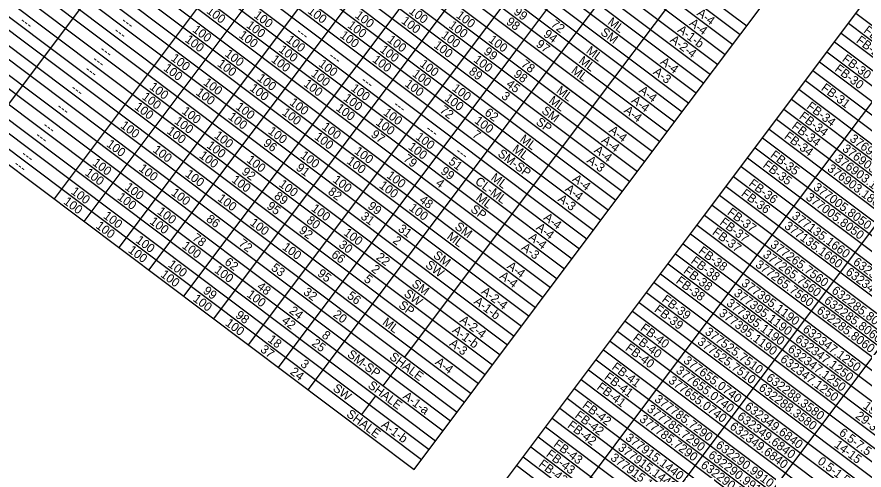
# Model space of a CAD drawing. Extents: x 627484.2 to 627517.5, y 367968.7 to 367996.9.
# Drawn here: x 627486.93 to 627492.24, y 367988.56 to 367991.4 of the extents above; entities that cross this region are included whole.
import ezdxf

# ---------------------------------------------------------------- set-up
doc = ezdxf.new("R2010")
doc.units = 0
doc.layers.add('Default', color=7, linetype='Continuous')

msp = doc.modelspace()

# ---------------------------------------------------------------- linework, layer by layer
at = {"layer": 'Default'}
for p, q in [((627486.2591, 367995.2795), (627491.502, 367991.3425)), ((627486.2181, 367995.2249), (627491.461, 367991.288)), ((627486.1713, 367995.1625), (627491.4142, 367991.2256)), ((627486.1245, 367995.1002), (627491.3674, 367991.1632)), ((627486.0776, 367995.0378), (627491.3205, 367991.1008)), ((627486.0308, 367994.9754), (627491.2737, 367991.0385)), ((627485.9898, 367994.9208), (627491.2327, 367990.9839)), ((627485.943, 367994.8585), (627491.1859, 367990.9215)), ((627485.8961, 367994.7961), (627491.139, 367990.8591)), ((627485.8552, 367994.7415), (627491.0981, 367990.8046)), ((627485.8083, 367994.6791), (627491.0512, 367990.7422)), ((627485.7615, 367994.6168), (627491.0044, 367990.6798)), ((627485.7146, 367994.5544), (627490.9576, 367990.6175)), ((627485.6678, 367994.492), (627490.9107, 367990.5551)), ((627485.621, 367994.4297), (627490.8639, 367990.4927)), ((627485.5741, 367994.3673), (627490.817, 367990.4303)), ((627485.5273, 367994.3049), (627490.7702, 367990.368)), ((627485.4805, 367994.2425), (627490.7234, 367990.3056)), ((627485.4395, 367994.188), (627490.6824, 367990.251)), ((627485.3926, 367994.1256), (627490.6356, 367990.1886)), ((627485.3458, 367994.0632), (627490.5887, 367990.1263)), ((627485.299, 367994.0008), (627490.5419, 367990.0639)), ((627485.258, 367993.9463), (627490.5009, 367990.0093)), ((627485.2112, 367993.8839), (627490.4541, 367989.9469)), ((627485.1643, 367993.8215), (627490.4072, 367989.8846)), ((627485.1175, 367993.7592), (627490.3604, 367989.8222)), ((627485.0706, 367993.6968), (627490.3136, 367989.7598)), ((627485.0297, 367993.6422), (627490.2726, 367989.7053)), ((627489.8738, 367991.3337), (627491.5774, 367993.6025)), ((627484.9828, 367993.5798), (627490.2257, 367989.6429)), ((627484.936, 367993.5175), (627490.1789, 367989.5805)), ((627484.895, 367993.4629), (627490.1379, 367989.5259)), ((627490.0609, 367991.1932), (627491.7646, 367993.462)), ((627490.248, 367991.0527), (627492.0571, 367993.4619)), ((627484.8482, 367993.4005), (627490.0911, 367989.4636)), ((627484.8013, 367993.3381), (627490.0442, 367989.4012)), ((627484.7604, 367993.2836), (627490.0033, 367989.3466)), ((627484.7135, 367993.2212), (627489.9564, 367989.2842)), ((627484.6667, 367993.1588), (627489.9096, 367989.2219)), ((627484.6198, 367993.0964), (627489.8628, 367989.1595)), ((627484.5789, 367993.0419), (627489.8218, 367989.1049)), ((627484.532, 367992.9795), (627489.7749, 367989.0425)), ((627490.9576, 367990.6175), (627492.7198, 367992.9642)), ((627484.491, 367992.9249), (627489.734, 367988.988)), ((627484.4442, 367992.8625), (627489.6871, 367988.9256)), ((627484.4032, 367992.808), (627489.6461, 367988.871)), ((627484.3564, 367992.7456), (627489.5993, 367988.8086)), ((627484.3096, 367992.6832), (627489.5525, 367988.7463)), ((627491.2374, 367990.1574), (627493.1196, 367992.664)), ((627484.2686, 367992.6286), (627489.5115, 367988.6917)), ((627484.2217, 367992.5663), (627489.4646, 367988.6293)), ((627484.1749, 367992.5039), (627489.4178, 367988.5669)), ((627491.5219, 367989.8462), (627493.451, 367992.4152)), ((627487.1646, 367990.2589), (627488.6575, 367992.247)), ((627490.4128, 367987.5698), (627493.8348, 367992.127)), ((627487.3517, 367990.1184), (627488.8446, 367992.1065)), ((627486.6968, 367990.6102), (627487.7331, 367991.9902)), ((627487.57, 367989.9545), (627489.0629, 367991.9426)), ((627487.7571, 367989.814), (627489.25, 367991.8021)), ((627490.7966, 367987.2816), (627494.2186, 367991.8387)), ((627487.9754, 367989.65), (627489.4683, 367991.6382)), ((627490.5365, 367990.8361), (627491.1278, 367991.6236)), ((627488.1626, 367989.5095), (627489.6555, 367991.4977)), ((627492.1858, 367991.4204), (627497.4287, 367987.4835)), ((627488.3809, 367989.3456), (627489.8738, 367991.3337)), ((627492.139, 367991.3581), (627497.3819, 367987.4211)), ((627492.0921, 367991.2957), (627497.335, 367987.3587)), ((627492.0511, 367991.2411), (627497.2941, 367987.3042)), ((627488.568, 367989.2051), (627490.0609, 367991.1932)), ((627492.0043, 367991.1787), (627497.2472, 367987.2418)), ((627491.9575, 367991.1164), (627497.2004, 367987.1794)), ((627488.7551, 367989.0646), (627490.248, 367991.0527)), ((627490.248, 367991.0527), (627490.9107, 367990.5551)), ((627491.9165, 367991.0618), (627497.1594, 367987.1248)), ((627491.8697, 367990.9994), (627497.1126, 367987.0625)), ((627491.8287, 367990.9448), (627497.0716, 367987.0079)), ((627489.3597, 367989.269), (627490.5365, 367990.8361)), ((627491.7818, 367990.8825), (627497.0247, 367986.9455)), ((627491.735, 367990.8201), (627496.9779, 367986.8832)), ((627491.6882, 367990.7577), (627496.9311, 367986.8208)), ((627491.6413, 367990.6954), (627496.8842, 367986.7584)), ((627491.6003, 367990.6408), (627496.8433, 367986.7038)), ((627489.4178, 367988.5669), (627490.9576, 367990.6175)), ((627491.5535, 367990.5784), (627496.7964, 367986.6415)), ((627491.5067, 367990.516), (627496.7496, 367986.5791)), ((627491.4657, 367990.4615), (627496.7086, 367986.5245)), ((627491.4189, 367990.3991), (627496.6618, 367986.4621)), ((627491.372, 367990.3367), (627496.6149, 367986.3998)), ((627491.331, 367990.2821), (627496.5739, 367986.3452)), ((627491.2842, 367990.2198), (627496.5271, 367986.2828)), ((627489.6976, 367988.1069), (627491.2374, 367990.1574)), ((627491.2374, 367990.1574), (627496.4803, 367986.2204)), ((627491.1905, 367990.095), (627496.4334, 367986.1581)), ((627491.1495, 367990.0404), (627496.3925, 367986.1035)), ((627491.1027, 367989.9781), (627496.3456, 367986.0411)), ((627491.0559, 367989.9157), (627496.2988, 367985.9787)), ((627490.029, 367987.8581), (627491.5219, 367989.8462)), ((627491.009, 367989.8533), (627496.2519, 367985.9164)), ((627490.9622, 367989.791), (627496.2051, 367985.854)), ((627490.9212, 367989.7364), (627496.1641, 367985.7994)), ((627490.8744, 367989.674), (627496.1173, 367985.7371)), ((627490.8275, 367989.6116), (627496.0705, 367985.6747)), ((627490.7866, 367989.5571), (627496.0295, 367985.6201)), ((627490.7397, 367989.4947), (627495.9826, 367985.5577)), ((627490.6929, 367989.4323), (627495.9358, 367985.4954)), ((627490.6461, 367989.3699), (627495.889, 367985.433)), ((627490.6051, 367989.3154), (627495.848, 367985.3784)), ((627490.5582, 367989.253), (627495.8011, 367985.316)), ((627489.2251, 367989.0897), (627489.3129, 367989.2066)), ((627490.5114, 367989.1906), (627495.7543, 367985.2537)), ((627490.4646, 367989.1282), (627495.7075, 367985.1913)), ((627490.4236, 367989.0737), (627495.6665, 367985.1367)), ((627489.0904, 367988.9103), (627489.1782, 367989.0273)), ((627490.3767, 367989.0113), (627495.6197, 367985.0743)), ((627490.3299, 367988.9489), (627495.5728, 367985.012)), ((627490.2831, 367988.8865), (627495.526, 367984.9496)), ((627490.2421, 367988.832), (627495.485, 367984.895)), ((627490.1953, 367988.7696), (627495.4382, 367984.8326)), ((627490.1484, 367988.7072), (627495.3913, 367984.7703)), ((627490.1016, 367988.6449), (627495.3445, 367984.7079)), ((627490.0606, 367988.5903), (627495.3035, 367984.6533))]:
    msp.add_line(p, q, dxfattribs=at)

# ---------------------------------------------------------------- texts
for s, p in [('100', (627488.1132, 367991.4265)), ('100', (627488.4096, 367991.399)), ('100', (627488.747, 367991.4261)), ('100', (627489.0434, 367991.3986)), ('100', (627489.3807, 367991.4257)), ('100', (627489.6771, 367991.3983)), ('99', (627490.0368, 367991.4208)), ('A-4', (627491.1846, 367991.4124)), ('---', (627486.9459, 367991.3641)), ('---', (627487.5797, 367991.3638)), ('100', (627488.3628, 367991.3366)), ('100', (627488.9965, 367991.3362)), ('100', (627489.3339, 367991.3633)), ('100', (627489.6303, 367991.3359)), ('98', (627489.9904, 367991.3581)), ('72', (627490.2707, 367991.3427)), ('ML', (627490.6263, 367991.3561)), ('A-4', (627491.1378, 367991.35)), ('---', (627487.5329, 367991.3014)), ('100', (627488.0254, 367991.3095)), ('---', (627488.6756, 367991.2968)), ('94', (627490.2237, 367991.2805)), ('SM', (627490.5812, 367991.2924)), ('A-1-b', (627491.0639, 367991.3079)), ('FB-29', (627492.2299, 367991.3042)), ('100', (627487.9786, 367991.2471)), ('100', (627488.3159, 367991.2742)), ('100', (627488.6123, 367991.2468)), ('100', (627488.9497, 367991.2739)), ('100', (627489.2461, 367991.2464)), ('100', (627489.5834, 367991.2735)), ('100', (627489.8798, 367991.246)), ('A-2-4', (627491.017, 367991.2456)), ('FB-29', (627492.1831, 367991.2418)), ('100', (627488.5655, 367991.1844)), ('100', (627489.1992, 367991.184)), ('100', (627489.5366, 367991.2111)), ('99', (627489.8495, 367991.1713)), ('97', (627490.1772, 367991.2178)), ('ML', (627490.4916, 367991.1768)), ('---', (627487.445, 367991.1844)), ('100', (627487.8908, 367991.1302)), ('100', (627488.2281, 367991.1573)), ('100', (627488.5186, 367991.122)), ('---', (627488.8783, 367991.1446)), ('100', (627489.1524, 367991.1217)), ('100', (627489.7861, 367991.1213)), ('ML', (627490.4448, 367991.1144)), ('FB-30', (627492.095, 367991.125)), ('---', (627487.3982, 367991.1221)), ('100', (627487.8439, 367991.0678)), ('100', (627488.1813, 367991.0949)), ('100', (627488.815, 367991.0946)), ('100', (627489.4488, 367991.0942)), ('78', (627490.0839, 367991.0928)), ('A-4', (627490.9563, 367991.1083)), ('FB-30', (627492.0482, 367991.0626)), ('---', (627487.3514, 367991.0597)), ('100', (627488.7682, 367991.0322)), ('100', (627489.4019, 367991.0318)), ('89', (627489.7558, 367991.0465)), ('98', (627490.037, 367991.0304)), ('ML', (627490.398, 367991.052)), ('A-3', (627490.911, 367991.0448)), ('100', (627488.0935, 367990.978)), ('100', (627488.4308, 367991.0051)), ('100', (627488.7214, 367990.9698)), ('---', (627489.081, 367990.9924)), ('100', (627489.3551, 367990.9694)), ('45', (627489.9905, 367990.9678)), ('---', (627487.2636, 367990.9427)), ('100', (627487.7561, 367990.9509)), ('100', (627488.0466, 367990.9156)), ('100', (627488.384, 367990.9427)), ('100', (627489.0177, 367990.9423)), ('100', (627489.6515, 367990.942)), ('ML', (627490.3043, 367990.9273)), ('A-4', (627490.8216, 367990.929)), ('FB-31', (627491.9632, 367990.9436)), ('100', (627487.7093, 367990.8885)), ('100', (627488.9709, 367990.88)), ('100', (627489.6047, 367990.8796)), ('3', (627489.9605, 367990.8928)), ('ML', (627490.2575, 367990.8649)), ('A-4', (627490.7748, 367990.8666)), ('---', (627487.1757, 367990.8258)), ('100', (627487.6624, 367990.8261)), ('100', (627488.2962, 367990.8258)), ('100', (627488.6335, 367990.8529)), ('100', (627488.9241, 367990.8176)), ('---', (627489.2837, 367990.8402)), ('72', (627489.5743, 367990.8049)), ('SM', (627490.2124, 367990.8012)), ('A-4', (627490.728, 367990.8042)), ('FB-34', (627491.8725, 367990.8288)), ('100', (627487.9588, 367990.7986)), ('100', (627488.2493, 367990.7634)), ('100', (627488.5867, 367990.7905)), ('100', (627489.2205, 367990.7901)), ('62', (627489.855, 367990.7891)), ('FB-34', (627491.8257, 367990.7664)), ('100', (627487.5746, 367990.7092)), ('100', (627487.912, 367990.7363)), ('100', (627488.8363, 367990.7006)), ('100', (627489.1736, 367990.7277)), ('100', (627489.7918, 367990.7391)), ('SP', (627490.1768, 367990.7304)), ('FB-34', (627491.7788, 367990.704)), ('---', (627487.0879, 367990.7088)), ('100', (627487.8651, 367990.6739)), ('100', (627488.1615, 367990.6464)), ('100', (627488.4989, 367990.6735)), ('97', (627489.1433, 367990.6529)), ('---', (627489.4864, 367990.688)), ('7', (627489.7777, 367990.6521)), ('A-4', (627490.6343, 367990.6795)), ('FB-34', (627491.732, 367990.6416)), ('---', (627487.0411, 367990.6465)), ('100', (627487.4868, 367990.5922)), ('96', (627488.4684, 367990.5989)), ('100', (627488.7894, 367990.6383)), ('100', (627489.4232, 367990.6379)), ('ML', (627490.076, 367990.6232)), ('A-4', (627490.5874, 367990.6171)), ('376903.1860', (627492.1426, 367990.626)), ('100', (627487.7773, 367990.557)), ('100', (627488.1147, 367990.5841)), ('100', (627489.039, 367990.5484)), ('100', (627489.3763, 367990.5755)), ('ML', (627490.0291, 367990.5608)), ('A-4', (627490.5406, 367990.5548)), ('376903.1860', (627492.0958, 367990.5636)), ('---', (627486.9533, 367990.5295)), ('100', (627488.0678, 367990.5217)), ('100', (627488.3642, 367990.4942)), ('100', (627488.7016, 367990.5213)), ('100', (627488.9921, 367990.486)), ('79', (627489.346, 367990.5008)), ('51', (627489.6294, 367990.4831)), ('---', (627489.6735, 367990.5474)), ('SM-SP', (627489.9376, 367990.532)), ('A-3', (627490.4954, 367990.4912)), ('FB-35', (627491.6452, 367990.5239)), ('376903.1860', (627492.0489, 367990.5012)), ('---', (627486.9064, 367990.4672)), ('100', (627487.399, 367990.4753)), ('100', (627487.6895, 367990.44)), ('91', (627488.6738, 367990.4446)), ('FB-35', (627491.5984, 367990.4616)), ('376903.1860', (627492.0021, 367990.4388)), ('100', (627487.3521, 367990.4129)), ('100', (627487.98, 367990.4047)), ('92', (627488.3338, 367990.4195)), ('100', (627489.2417, 367990.3962)), ('99', (627489.5799, 367990.4226)), ('ML', (627489.8945, 367990.3815)), ('100', (627488.2706, 367990.3695)), ('100', (627488.5669, 367990.342)), ('100', (627488.9043, 367990.3691)), ('100', (627489.1948, 367990.3338)), ('4', (627489.5491, 367990.3483)), ('CL-ML', (627489.7953, 367990.3584)), ('A-4', (627490.406, 367990.3754)), ('FB-36', (627491.5097, 367990.3453)), ('377005.8050', (627491.9143, 367990.3219)), ('100', (627487.2643, 367990.296)), ('100', (627487.6017, 367990.3231)), ('100', (627487.8922, 367990.2878)), ('89', (627488.5366, 367990.2673)), ('82', (627488.8739, 367990.2944)), ('A-4', (627490.3591, 367990.3131)), ('FB-36', (627491.4628, 367990.2829)), ('100', (627487.2175, 367990.2336)), ('100', (627487.5548, 367990.2607)), ('100', (627488.1827, 367990.2525)), ('48', (627489.4457, 367990.243)), ('ML', (627489.8008, 367990.2568)), ('A-3', (627490.3139, 367990.2495)), ('377005.8050', (627491.8674, 367990.2595)), ('100', (627487.8044, 367990.1708)), ('95', (627488.4905, 367990.2043)), ('100', (627488.7697, 367990.1898)), ('99', (627489.1235, 367990.2045)), ('100', (627489.382, 367990.1933)), ('SP', (627489.767, 367990.1846)), ('FB-37', (627491.3752, 367990.1658)), ('100', (627487.467, 367990.1437)), ('86', (627488.1113, 367990.1233)), ('80', (627488.7391, 367990.1152)), ('31', (627489.0793, 367990.1402)), ('A-4', (627490.2245, 367990.1337)), ('377135.1660', (627491.7796, 367990.1426)), ('100', (627487.4202, 367990.0814)), ('100', (627487.7576, 367990.1085)), ('100', (627488.3855, 367990.1003)), ('31', (627489.3132, 367990.062)), ('SM', (627489.6679, 367990.0761)), ('A-4', (627490.1776, 367990.0714)), ('FB-37', (627491.3284, 367990.1034)), ('377135.1660', (627491.7328, 367990.0802)), ('78', (627488.0241, 367990.0059)), ('92', (627488.6924, 367990.0527)), ('100', (627488.9724, 367990.0376)), ('ML', (627489.6193, 367990.0151)), ('A-4', (627490.1308, 367990.009)), ('FB-37', (627491.2815, 367990.0411)), ('100', (627487.6697, 367989.9915)), ('100', (627487.9603, 367989.9562)), ('72', (627488.3141, 367989.971)), ('30', (627488.9418, 367989.963)), ('2', (627489.28, 367989.9895)), ('377265.7560', (627491.645, 367989.9633)), ('100', (627487.6229, 367989.9291)), ('100', (627488.5882, 367989.9481)), ('66', (627488.895, 367989.9005)), ('A-3', (627490.0855, 367989.9454)), ('FB-38', (627491.1941, 367989.9238)), ('377265.7560', (627491.5981, 367989.9009)), ('62', (627488.2263, 367989.8541)), ('22', (627489.1759, 367989.8847)), ('SM', (627489.5333, 367989.8968)), ('FB-38', (627491.1473, 367989.8614)), ('632344.5490', (627492.1634, 367989.8544)), ('100', (627487.8724, 367989.8393)), ('100', (627488.163, 367989.804)), ('53', (627488.5181, 367989.8178)), ('2', (627489.1453, 367989.8101)), ('SW', (627489.4842, 367989.8361)), ('A-4', (627489.9961, 367989.8297)), ('FB-38', (627491.1005, 367989.7991)), ('377265.7560', (627491.5513, 367989.8385)), ('632344.5490', (627492.1166, 367989.792)), ('100', (627487.8256, 367989.7769)), ('95', (627488.8081, 367989.7829)), ('5', (627489.0993, 367989.7472)), ('A-4', (627489.9493, 367989.7673)), ('FB-38', (627491.0536, 367989.7367)), ('48', (627488.4295, 367989.7015)), ('SM', (627489.3986, 367989.7175)), ('377395.1190', (627491.4635, 367989.7216)), ('99', (627488.0916, 367989.6747)), ('100', (627488.3657, 367989.6518)), ('32', (627488.7195, 367989.6666)), ('56', (627488.9943, 367989.6431)), ('SW', (627489.3496, 367989.6568)), ('A-2-4', (627489.8344, 367989.6707)), ('377395.1190', (627491.4166, 367989.6592)), ('632285.8060', (627492.0288, 367989.675)), ('100', (627488.0283, 367989.6247)), ('SP', (627489.3162, 367989.5843)), ('A-1-b', (627489.7876, 367989.6083)), ('FB-39', (627490.9653, 367989.6201)), ('377395.1190', (627491.3698, 367989.5968)), ('632285.8060', (627491.9819, 367989.6127)), ('24', (627488.6315, 367989.5498)), ('20', (627488.9064, 367989.5262)), ('FB-39', (627490.9185, 367989.5577)), ('377395.1190', (627491.323, 367989.5344)), ('632285.8060', (627491.9351, 367989.5503)), ('98', (627488.2948, 367989.5221)), ('42', (627488.5848, 367989.4872)), ('ML', (627489.2154, 367989.4771)), ('A-2-4', (627489.6998, 367989.4914)), ('100', (627488.231, 367989.4725)), ('A-1-b', (627489.653, 367989.429)), ('FB-40', (627490.8304, 367989.4409)), ('632347.1250', (627491.8473, 367989.4333)), ('18', (627488.4975, 367989.3699)), ('8', (627488.8356, 367989.3965)), ('FB-40', (627490.7836, 367989.3786)), ('377525.7510', (627491.2351, 367989.4175)), ('632347.1250', (627491.8005, 367989.371)), ('25', (627488.7728, 367989.3461)), ('A-3', (627489.6347, 367989.3451)), ('FB-40', (627490.7368, 367989.3162)), ('377525.7510', (627491.1883, 367989.3551)), ('37', (627488.4503, 367989.3078)), ('SM-SP', (627488.995, 367989.2768)), ('SHALE', (627489.2588, 367989.2616)), ('632347.1250', (627491.7536, 367989.3086)), ('3', (627488.7017, 367989.2166)), ('A-4', (627489.5453, 367989.2293)), ('377655.0740', (627491.1005, 367989.2382)), ('632347.1250', (627491.7068, 367989.2462)), ('24', (627488.6371, 367989.1676)), ('FB-41', (627490.6518, 367989.1971)), ('377655.0740', (627491.0536, 367989.1758)), ('FB-41', (627490.6049, 367989.1348)), ('377655.0740', (627491.0068, 367989.1134)), ('632288.3580', (627491.619, 367989.1293)), ('SW', (627488.9046, 367989.0642)), ('SHALE', (627489.1241, 367989.0823)), ('FB-41', (627490.5581, 367989.0724)), ('632288.3580', (627491.5721, 367989.0669)), ('A-1-a', (627489.3434, 367989.0152)), ('377785.7290', (627490.919, 367988.9965)), ('FB-42', (627490.4677, 367988.9574)), ('632349.6840', (627491.4843, 367988.9499)), ('19-20', (627492.2255, 367988.9543)), ('SHALE', (627488.9895, 367988.903)), ('FB-42', (627490.4208, 367988.895)), ('377785.7290', (627490.8722, 367988.9341)), ('29-30', (627492.1786, 367988.8919)), ('FB-42', (627490.374, 367988.8327)), ('377785.7290', (627490.8253, 367988.8717)), ('632349.6840', (627491.4375, 367988.8876)), ('A-1-b', (627489.208, 367988.8364)), ('632349.6840', (627491.3906, 367988.8252)), ('6.5-7.5', (627492.0756, 367988.7864)), ('377915.1440', (627490.7375, 367988.7548)), ('FB-43', (627490.2875, 367988.7147)), ('377915.1440', (627490.6907, 367988.6924)), ('632290.9910', (627491.3028, 367988.7083)), ('14-15', (627492.045, 367988.7118)), ('FB-43', (627490.2407, 367988.6523)), ('377915.1440', (627490.6438, 367988.63)), ('632290.9910', (627491.256, 367988.6459)), ('FB-43', (627490.1938, 367988.59)), ('632290.9910', (627491.2091, 367988.5835)), ('0.5-1.5', (627491.9409, 367988.6071))]:
    msp.add_text(s, height=0.055, rotation=323.0968, dxfattribs=at).set_placement(p)

doc.saveas('drawing.dxf')
